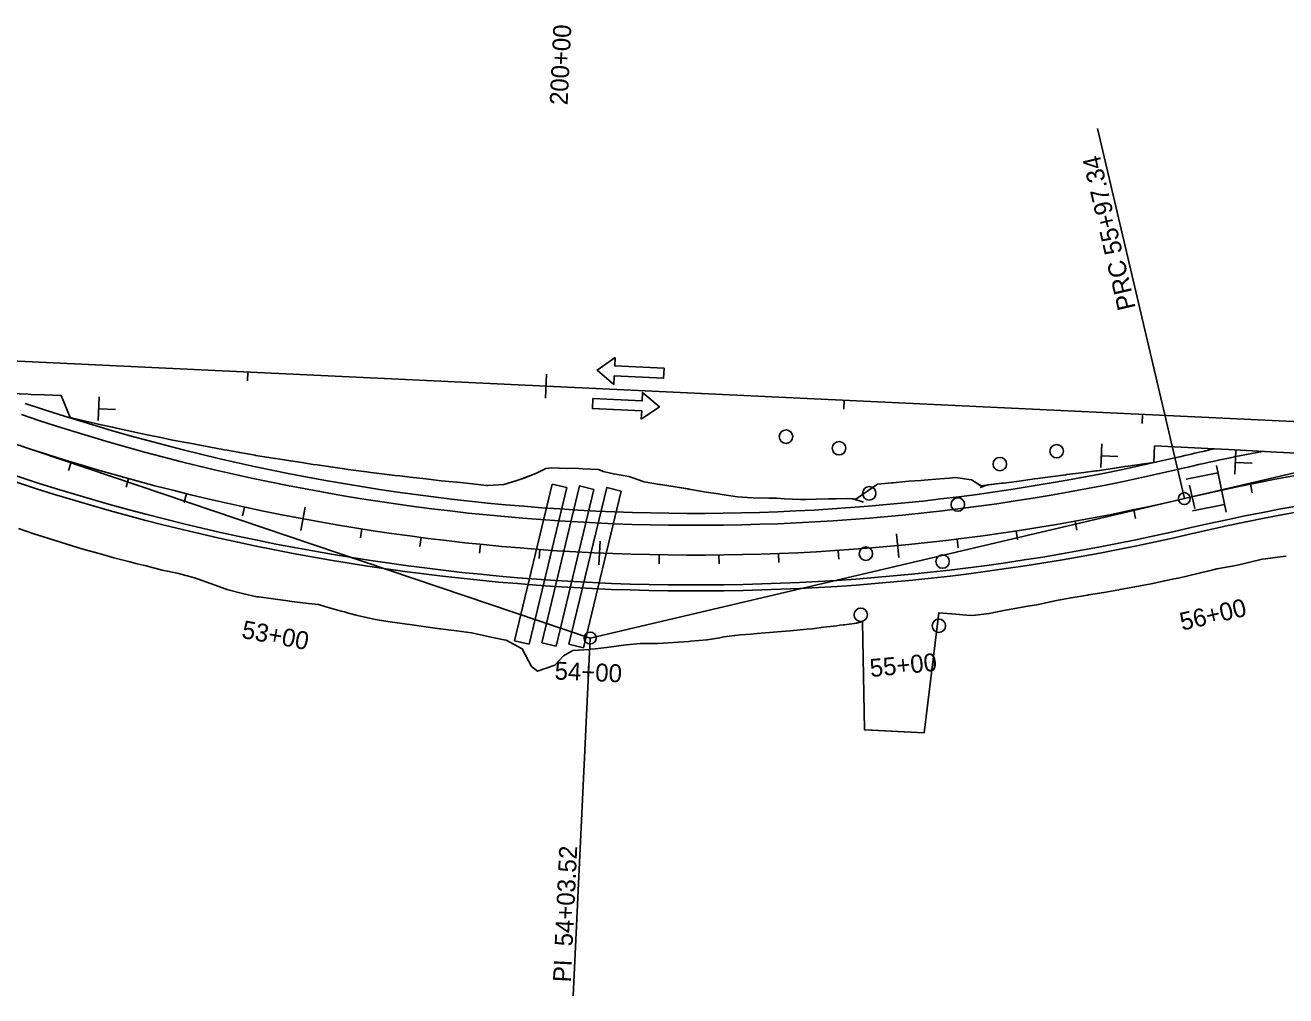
# Model space of a CAD drawing. Extents: x 1140339 to 1165793, y 1646213 to 1669071.
# Drawn here: x 1149058.7 to 1149480.8, y 1657272.9 to 1657598 of the extents above; entities that cross this region are included whole.
import ezdxf

# ---------------------------------------------------------------- set-up
doc = ezdxf.new("R2010")
doc.units = 0
for name, color, linetype in [('Level 47', 7, 'Continuous'), ('R_Horz Alg', 7, 'Continuous'), ('R_Horz Alg Annot', 7, 'Continuous'), ('R_MOT', 7, 'Continuous'), ('R_No Plot', 7, 'Continuous'), ('R_Proposed Const Limits_Cut', 7, 'Continuous'), ('R_Proposed Const Limits_Fill', 7, 'Continuous'), ('R_Proposed Road_Lane', 7, 'Continuous'), ('R_Proposed Road_Shoulder', 7, 'Continuous'), ('R_Water', 7, 'Continuous')]:
    doc.layers.add(name, color=color, linetype=linetype)

msp = doc.modelspace()

# ---------------------------------------------------------------- linework, layer by layer
at = {"layer": 'Level 47'}
for centre in [(1149313.45, 1657460.19), (1149331.21, 1657456.3), (1149404.1, 1657455.3), (1149385.06, 1657451), (1149341.33, 1657441.19), (1149371, 1657437.46), (1149340.2, 1657420.98), (1149365.89, 1657418.35), (1149338.48, 1657400.51), (1149364.64, 1657396.82)]:
    msp.add_circle(centre, 2.25, dxfattribs=at)
at = {"layer": 'R_Horz Alg'}
msp.add_line((1148434, 1657515.04), (1150132.09, 1657434.46), dxfattribs=at)
for centre, start, end in [((1149283.16, 1658136.69), 251.35438, 283.21228), ((1149610.54, 1656742.21), 87.28333, 103.21228)]:
    msp.add_arc(centre, 716.2, start, end, dxfattribs=at)
at = {"layer": 'R_Horz Alg Annot'}
for p, q in [((1149446.85, 1657439.45), (1149417.75, 1657563.41)), ((1149446.85, 1657439.45), (1149544.4, 1657462.35)), ((1149054.18, 1657458.08), (1149247.86, 1657392.73)), ((1149247.86, 1657392.73), (1149446.85, 1657439.45))]:
    msp.add_line(p, q, dxfattribs=at)
for points in [[(1149133.07, 1657478.87), (1149133.21, 1657481.86)], [(1149233.29, 1657481.12), (1149232.91, 1657473.13)], [(1149332.84, 1657469.39), (1149332.98, 1657472.38)], [(1149432.73, 1657464.65), (1149432.87, 1657467.64)], [(1149073.19, 1657448.82), (1149074.06, 1657451.69)], [(1149092.48, 1657443.23), (1149093.27, 1657446.12)], [(1149448.55, 1657443.95), (1149450.34, 1657436.16)], [(1149469.59, 1657441.34), (1149468.99, 1657444.28)], [(1149111.91, 1657438.17), (1149112.63, 1657441.09)], [(1149131.48, 1657433.67), (1149132.12, 1657436.6)], [(1149152.46, 1657436.59), (1149150.99, 1657428.72)], [(1149430.54, 1657432.75), (1149429.93, 1657435.69)], [(1149410.83, 1657428.91), (1149410.3, 1657431.87)], [(1149170.96, 1657426.3), (1149171.43, 1657429.26)], [(1149190.84, 1657423.44), (1149191.23, 1657426.42)], [(1149350.49, 1657427.68), (1149351.25, 1657419.72)], [(1149371.12, 1657422.89), (1149370.75, 1657425.87)], [(1149391.02, 1657425.63), (1149390.57, 1657428.59)], [(1149210.79, 1657421.14), (1149211.1, 1657424.13)], [(1149230.8, 1657419.4), (1149231.02, 1657422.39)], [(1149251.16, 1657425.21), (1149250.81, 1657417.22)], [(1149331.14, 1657419.09), (1149330.94, 1657422.09)], [(1149270.92, 1657417.59), (1149270.97, 1657420.59)], [(1149291.01, 1657417.53), (1149290.97, 1657420.53)], [(1149311.08, 1657418.03), (1149310.97, 1657421.03)], [(1149247.86, 1657392.73), (1149242.17, 1657272.86)]]:
    msp.add_lwpolyline(points, dxfattribs=at)
for centre in [(1149446.85, 1657439.45), (1149247.86, 1657392.73)]:
    msp.add_circle(centre, 2, dxfattribs=at)
at = {"layer": 'R_MOT'}
for p, q in [((1149083.13, 1657465.57), (1149083.46, 1657473.56)), ((1149083.41, 1657469.54), (1149088.86, 1657469.31)), ((1149418.89, 1657449.84), (1149419.22, 1657457.83)), ((1149463.81, 1657447.6), (1149464.14, 1657455.59)), ((1149419.17, 1657453.81), (1149424.63, 1657453.58)), ((1149464.09, 1657451.57), (1149469.55, 1657451.35)), ((1149447.41, 1657445.93), (1149458.11, 1657448.12)), ((1149460.82, 1657434.9), (1149457.61, 1657450.58)), ((1149449.59, 1657435.3), (1149460.29, 1657437.49))]:
    msp.add_line(p, q, dxfattribs=at)
for points in [[(1149256.22, 1657486.69), (1149250.18, 1657482.48), (1149255.8, 1657477.7), (1149255.93, 1657480.51), (1149272.46, 1657479.73), (1149272.62, 1657483.1), (1149256.09, 1657483.88)], [(1149264.99, 1657466), (1149271.04, 1657470.22), (1149265.42, 1657474.99), (1149265.28, 1657472.18), (1149248.75, 1657472.96), (1149248.59, 1657469.59), (1149265.12, 1657468.81)]]:
    msp.add_lwpolyline(points, close=True, dxfattribs=at)
at = {"layer": 'R_No Plot'}
for points in [[(1149048.03, 1657474.84), (1149059.68, 1657474.39), (1149059.68, 1657474.39), (1149060.59, 1657474.36), (1149065.14, 1657474.19), (1149070.58, 1657473.98), (1149070.71, 1657473.97), (1149073.75, 1657466.59), (1149078.29, 1657465.53), (1149078.9, 1657465.38), (1149084.04, 1657464.19), (1149087.85, 1657463.32), (1149089.19, 1657463.02), (1149094.34, 1657461.87), (1149097.43, 1657461.23), (1149099.5, 1657460.8), (1149104.67, 1657459.74), (1149107.02, 1657459.27), (1149109.83, 1657458.71), (1149115.01, 1657457.73), (1149115.52, 1657457.63), (1149116.63, 1657457.43), (1149120.18, 1657456.78), (1149125.35, 1657455.82), (1149126.24, 1657455.65), (1149130.51, 1657454.83), (1149135.69, 1657453.94), (1149135.85, 1657453.92), (1149140.88, 1657453.09), (1149145.49, 1657452.37), (1149146.06, 1657452.28), (1149151.25, 1657451.49), (1149155.13, 1657450.9), (1149156.44, 1657450.7), (1149161.63, 1657449.94), (1149164.77, 1657449.5), (1149166.82, 1657449.22), (1149172.01, 1657448.53), (1149173.06, 1657448.39), (1149174.43, 1657448.21), (1149177.21, 1657447.85), (1149182.41, 1657447.21), (1149184.08, 1657447.01), (1149187.61, 1657446.6), (1149192.81, 1657446.02), (1149193.75, 1657445.9), (1149198.01, 1657445.4), (1149203.23, 1657444.94), (1149203.43, 1657444.93), (1149208.43, 1657444.38), (1149213.09, 1657443.83), (1149213.62, 1657443.77), (1149218.92, 1657444.16), (1149222.98, 1657445.38), (1149224.3, 1657445.78), (1149225.43, 1657446.22)], [(1149436.62, 1657451.54), (1149436.91, 1657457.1), (1149456.99, 1657456.08)], [(1149456.99, 1657456.08), (1149461.68, 1657455.84), (1149477.76, 1657455.02), (1149493.85, 1657454.2), (1149514.25, 1657453.18), (1149534.65, 1657452.17), (1149548.5, 1657451.54), (1149562.35, 1657450.92), (1149576.21, 1657450.3), (1149590.06, 1657449.68), (1149605.38, 1657448.9), (1149620.71, 1657448.13), (1149636.03, 1657447.36), (1149643.98, 1657446.96)], [(1149378.8, 1657443.73), (1149385.78, 1657444.58), (1149386.3, 1657444.64), (1149388.1, 1657444.86), (1149391.51, 1657445.3), (1149396.72, 1657446.02), (1149397.79, 1657446.17), (1149401.94, 1657446.73), (1149407.15, 1657447.45), (1149407.48, 1657447.49), (1149412.39, 1657448.09), (1149417.2, 1657448.71), (1149417.62, 1657448.76), (1149422.84, 1657449.51), (1149426.9, 1657450.14), (1149428.06, 1657450.32), (1149433.29, 1657451.06), (1149436.62, 1657451.54)], [(1149225.43, 1657446.22), (1149229.69, 1657447.87), (1149233, 1657449.55), (1149235.02, 1657449.78), (1149240.19, 1657449.53), (1149242.64, 1657449.59), (1149245.37, 1657449.46), (1149250.54, 1657449.24), (1149250.54, 1657449.24), (1149250.95, 1657449.07), (1149252.21, 1657448.56), (1149255.65, 1657447.69), (1149260.81, 1657446.85), (1149261.77, 1657446.49), (1149265.95, 1657445.03), (1149271.13, 1657444.18), (1149271.38, 1657444.15), (1149276.33, 1657443.38), (1149280.73, 1657442.68)], [(1149336.8, 1657439.25), (1149344.13, 1657444.31), (1149348.88, 1657444.71), (1149349.33, 1657444.75), (1149350.3, 1657444.84), (1149354.53, 1657445.24), (1149358.55, 1657445.55), (1149359.74, 1657445.64), (1149364.96, 1657446.03), (1149368.24, 1657446.29), (1149370.17, 1657446.45), (1149375.55, 1657445.68), (1149378.8, 1657443.73)], [(1149280.73, 1657442.68), (1149281.04, 1657442.63), (1149281.54, 1657442.53), (1149286.76, 1657441.55), (1149290.75, 1657441.01), (1149291.99, 1657440.85), (1149297.24, 1657440.04), (1149300.5, 1657439.76), (1149302.48, 1657439.71), (1149307.73, 1657439.61), (1149310.25, 1657439.57), (1149312.99, 1657439.37), (1149318.25, 1657439.11), (1149320.02, 1657439.14), (1149323.5, 1657439.21), (1149327.71, 1657439.31), (1149328.75, 1657439.34), (1149329.78, 1657439.37), (1149330.2, 1657439.38), (1149334.01, 1657439.49), (1149336.8, 1657439.25)], [(1149480.94, 1657420.17), (1149478.09, 1657419.83), (1149474.03, 1657419.3), (1149472.95, 1657419.09), (1149467.89, 1657417.92), (1149464.63, 1657417.16), (1149462.84, 1657416.75), (1149457.72, 1657415.85), (1149455.17, 1657415.27), (1149452.67, 1657414.67), (1149452.67, 1657414.67), (1149447.26, 1657413.33), (1149445.27, 1657412.94), (1149441.78, 1657412.27), (1149436.35, 1657411.02), (1149435.15, 1657410.75), (1149430.88, 1657409.95), (1149425.39, 1657409), (1149424.96, 1657408.92), (1149419.92, 1657407.93), (1149414.76, 1657407.15), (1149414.41, 1657407.1), (1149408.91, 1657406.22), (1149404.56, 1657405.39), (1149403.45, 1657405.14), (1149397.99, 1657403.97), (1149394.4, 1657403.35), (1149392.49, 1657403.05), (1149391.95, 1657402.96), (1149387.01, 1657402.02), (1149384.2, 1657401.48), (1149381.52, 1657400.98), (1149376, 1657400.25), (1149373.89, 1657400.42), (1149370.33, 1657400.71), (1149364.67, 1657401.2), (1149359.74, 1657360.99), (1149340.06, 1657361.98), (1149339.76, 1657361.94), (1149339.1, 1657398.26), (1149337.05, 1657397.75), (1149333.05, 1657397.17), (1149332.61, 1657397.11), (1149331.52, 1657396.98), (1149330.42, 1657396.84), (1149325.98, 1657396.31), (1149322.31, 1657395.86), (1149320.44, 1657395.66), (1149314.88, 1657395.17), (1149311.98, 1657394.94), (1149309.31, 1657394.73), (1149303.75, 1657394.23), (1149301.64, 1657394.05), (1149298.17, 1657393.77), (1149292.6, 1657393.12), (1149291.28, 1657392.83), (1149287.01, 1657392.17), (1149281.42, 1657391.66), (1149280.89, 1657391.61), (1149275.82, 1657391.24), (1149270.47, 1657390.93), (1149270.21, 1657390.92), (1149264.6, 1657390.84), (1149260.04, 1657390.42), (1149258.97, 1657390.28), (1149253.33, 1657389.58), (1149249.54, 1657389.13), (1149248.13, 1657388.97), (1149247.68, 1657388.91), (1149247.67, 1657388.91), (1149242.02, 1657388.54), (1149238.94, 1657386.77), (1149236.07, 1657383.65), (1149230.25, 1657381.61), (1149228.16, 1657383.16), (1149225.13, 1657389.16), (1149219.72, 1657392), (1149218.36, 1657392.28), (1149214.18, 1657393.15), (1149208.66, 1657394.33), (1149208.1, 1657394.46), (1149203.11, 1657395.1), (1149197.77, 1657395.8), (1149197.55, 1657395.83), (1149192, 1657396.59), (1149187.45, 1657397.22), (1149186.45, 1657397.36), (1149180.9, 1657398.13), (1149177.15, 1657398.72), (1149175.37, 1657399.07), (1149169.89, 1657400.26), (1149166.98, 1657401.06), (1149165.55, 1657401.46), (1149164.46, 1657401.76), (1149159.05, 1657403.29), (1149156.92, 1657403.91), (1149153.55, 1657404.31), (1149148, 1657405), (1149146.6, 1657405.18), (1149142.44, 1657405.73), (1149136.89, 1657406.49), (1149136.28, 1657406.57), (1149131.41, 1657407.63), (1149126.17, 1657409.03), (1149126, 1657409.09), (1149120.69, 1657410.96), (1149116.31, 1657412.54), (1149115.4, 1657412.87), (1149110, 1657414.31), (1149106.26, 1657415.12), (1149105.09, 1657415.38), (1149104.55, 1657415.51), (1149099.13, 1657416.86), (1149096.19, 1657417.62), (1149093.72, 1657418.24), (1149088.32, 1657419.63), (1149086.15, 1657420.23), (1149082.94, 1657421.14), (1149077.57, 1657422.65), (1149076.17, 1657423.06), (1149072.22, 1657424.26), (1149066.89, 1657425.94), (1149066.26, 1657426.14), (1149061.58, 1657427.64), (1149056.41, 1657429.39)]]:
    msp.add_lwpolyline(points, dxfattribs=at)
at = {"layer": 'R_Proposed Const Limits_Cut'}
msp.add_lwpolyline([(1149339.17, 1657440.84), (1149339.44, 1657441.07), (1149344.13, 1657444.31), (1149348.88, 1657444.71), (1149349.33, 1657444.75), (1149350.3, 1657444.84), (1149354.53, 1657445.24), (1149358.55, 1657445.55), (1149359.74, 1657445.64), (1149364.96, 1657446.03), (1149368.24, 1657446.29), (1149370.17, 1657446.45), (1149375.55, 1657445.68), (1149378.36, 1657443.99)], dxfattribs=at)
at = {"layer": 'R_Proposed Const Limits_Fill'}
for points in [[(1149048.03, 1657474.84), (1149059.68, 1657474.39), (1149059.68, 1657474.39), (1149060.59, 1657474.36), (1149065.14, 1657474.19), (1149070.58, 1657473.98), (1149070.71, 1657473.97), (1149073.75, 1657466.59), (1149078.29, 1657465.53), (1149078.9, 1657465.38), (1149084.04, 1657464.19), (1149087.85, 1657463.32), (1149089.19, 1657463.02), (1149094.34, 1657461.87), (1149097.43, 1657461.23), (1149099.5, 1657460.8), (1149104.67, 1657459.74), (1149107.02, 1657459.27), (1149109.83, 1657458.71), (1149115.01, 1657457.73), (1149115.52, 1657457.63), (1149116.63, 1657457.43), (1149120.18, 1657456.78), (1149125.35, 1657455.82), (1149126.24, 1657455.65), (1149130.51, 1657454.83), (1149135.69, 1657453.94), (1149135.85, 1657453.92), (1149140.88, 1657453.09), (1149145.49, 1657452.37), (1149146.06, 1657452.28), (1149151.25, 1657451.49), (1149155.13, 1657450.9), (1149156.44, 1657450.7), (1149161.63, 1657449.94), (1149164.77, 1657449.5), (1149166.82, 1657449.22), (1149172.01, 1657448.53), (1149173.06, 1657448.39), (1149174.43, 1657448.21), (1149177.21, 1657447.85), (1149182.41, 1657447.21), (1149184.08, 1657447.01), (1149187.61, 1657446.6), (1149192.81, 1657446.02), (1149193.75, 1657445.9), (1149198.01, 1657445.4), (1149203.23, 1657444.94), (1149203.43, 1657444.93), (1149208.43, 1657444.38), (1149213.09, 1657443.83), (1149213.62, 1657443.77), (1149218.92, 1657444.16), (1149222.98, 1657445.38), (1149224.3, 1657445.78), (1149229.69, 1657447.87), (1149233, 1657449.55), (1149235.02, 1657449.78), (1149240.19, 1657449.53), (1149242.64, 1657449.59), (1149245.37, 1657449.46), (1149250.54, 1657449.24), (1149250.54, 1657449.24), (1149250.95, 1657449.07), (1149252.21, 1657448.56), (1149255.65, 1657447.69), (1149260.81, 1657446.85), (1149261.77, 1657446.49), (1149265.95, 1657445.03), (1149271.13, 1657444.18), (1149271.38, 1657444.15), (1149276.33, 1657443.38), (1149281.04, 1657442.63), (1149281.54, 1657442.53), (1149286.76, 1657441.55), (1149290.75, 1657441.01), (1149291.99, 1657440.85), (1149297.24, 1657440.04), (1149300.5, 1657439.76), (1149302.48, 1657439.71), (1149307.73, 1657439.61), (1149310.25, 1657439.57), (1149312.99, 1657439.37), (1149318.25, 1657439.11), (1149320.02, 1657439.14), (1149323.5, 1657439.21), (1149327.71, 1657439.31), (1149328.75, 1657439.34), (1149329.78, 1657439.37), (1149330.2, 1657439.38), (1149334.01, 1657439.49), (1149335.99, 1657439.32), (1149339.38, 1657438.19)], [(1149436.62, 1657451.54), (1149436.91, 1657457.1), (1149456.99, 1657456.08)], [(1149378.48, 1657443.13), (1149381.08, 1657444), (1149385.78, 1657444.58), (1149386.3, 1657444.64), (1149388.1, 1657444.86), (1149391.51, 1657445.3), (1149396.72, 1657446.02), (1149397.79, 1657446.17), (1149401.94, 1657446.73), (1149407.15, 1657447.45), (1149407.48, 1657447.49), (1149412.39, 1657448.09), (1149417.2, 1657448.71), (1149417.62, 1657448.76), (1149422.84, 1657449.51), (1149426.9, 1657450.14), (1149428.06, 1657450.32), (1149433.29, 1657451.06), (1149436.62, 1657451.54)], [(1149056.41, 1657429.39), (1149061.58, 1657427.64), (1149066.26, 1657426.14), (1149066.89, 1657425.94), (1149072.22, 1657424.26), (1149076.17, 1657423.06), (1149077.57, 1657422.65), (1149082.94, 1657421.14), (1149086.15, 1657420.23), (1149088.32, 1657419.63), (1149093.72, 1657418.24), (1149096.19, 1657417.62), (1149099.13, 1657416.86), (1149104.55, 1657415.51), (1149105.09, 1657415.38), (1149106.26, 1657415.12), (1149110, 1657414.31), (1149115.4, 1657412.87), (1149116.31, 1657412.54), (1149120.69, 1657410.96), (1149126, 1657409.09), (1149126.17, 1657409.03), (1149131.41, 1657407.63), (1149136.28, 1657406.57), (1149136.89, 1657406.49), (1149142.44, 1657405.73), (1149146.6, 1657405.18), (1149148, 1657405), (1149153.55, 1657404.31), (1149156.92, 1657403.91), (1149159.05, 1657403.29), (1149164.46, 1657401.76), (1149165.55, 1657401.46), (1149166.98, 1657401.06), (1149169.89, 1657400.26), (1149175.37, 1657399.07), (1149177.15, 1657398.72), (1149180.9, 1657398.13), (1149186.45, 1657397.36), (1149187.45, 1657397.22), (1149192, 1657396.59), (1149197.55, 1657395.83), (1149197.77, 1657395.8), (1149203.11, 1657395.1), (1149208.1, 1657394.46), (1149208.66, 1657394.33), (1149214.18, 1657393.15), (1149218.36, 1657392.28), (1149219.72, 1657392), (1149225.13, 1657389.16), (1149228.16, 1657383.16), (1149230.25, 1657381.61), (1149236.07, 1657383.65), (1149238.94, 1657386.77), (1149242.02, 1657388.54), (1149247.67, 1657388.91), (1149247.68, 1657388.91), (1149248.13, 1657388.97), (1149249.54, 1657389.13), (1149253.33, 1657389.58), (1149258.97, 1657390.28), (1149260.04, 1657390.42), (1149264.6, 1657390.84), (1149270.21, 1657390.92), (1149270.47, 1657390.93), (1149275.82, 1657391.24), (1149280.89, 1657391.61), (1149281.42, 1657391.66), (1149287.01, 1657392.17), (1149291.28, 1657392.83), (1149292.6, 1657393.12), (1149298.17, 1657393.77), (1149301.64, 1657394.05), (1149303.75, 1657394.23), (1149309.31, 1657394.73), (1149311.98, 1657394.94), (1149314.88, 1657395.17), (1149320.44, 1657395.66), (1149322.31, 1657395.86), (1149325.98, 1657396.31), (1149330.42, 1657396.84), (1149331.52, 1657396.98), (1149332.61, 1657397.11), (1149333.05, 1657397.17), (1149337.05, 1657397.75), (1149339.1, 1657398.26), (1149339.76, 1657361.94), (1149359.74, 1657360.99), (1149364.67, 1657401.2), (1149370.33, 1657400.71), (1149373.89, 1657400.42), (1149376, 1657400.25), (1149381.52, 1657400.98), (1149384.2, 1657401.48), (1149387.01, 1657402.02), (1149391.95, 1657402.96), (1149392.49, 1657403.05), (1149394.4, 1657403.35), (1149397.99, 1657403.97), (1149403.45, 1657405.14), (1149404.56, 1657405.39), (1149408.91, 1657406.22), (1149414.41, 1657407.1), (1149414.76, 1657407.15), (1149419.92, 1657407.93), (1149424.96, 1657408.92), (1149425.39, 1657409), (1149430.88, 1657409.95), (1149435.15, 1657410.75), (1149436.35, 1657411.02), (1149441.78, 1657412.27), (1149445.27, 1657412.94), (1149447.26, 1657413.33), (1149452.67, 1657414.67), (1149452.67, 1657414.67), (1149455.17, 1657415.27), (1149457.72, 1657415.85), (1149462.84, 1657416.75), (1149464.63, 1657417.16), (1149467.89, 1657417.92), (1149472.95, 1657419.09), (1149474.03, 1657419.3), (1149478.09, 1657419.83), (1149480.94, 1657420.17)]]:
    msp.add_lwpolyline(points, dxfattribs=at)
at = {"layer": 'R_Proposed Road_Lane'}
msp.add_lwpolyline([(1149643.98, 1657446.96), (1149636.03, 1657447.36), (1149620.71, 1657448.13), (1149605.38, 1657448.9), (1149590.06, 1657449.68), (1149576.21, 1657450.3), (1149562.35, 1657450.92), (1149548.5, 1657451.54), (1149534.65, 1657452.17), (1149514.25, 1657453.18), (1149493.85, 1657454.2), (1149477.76, 1657455.02), (1149461.68, 1657455.84), (1149456.99, 1657456.08)], dxfattribs=at)
for centre, radius, start, end in [((1149283.16, 1658136.69), 706.2, 251.35438, 283.21228), ((1149610.54, 1656742.21), 726.2, 100.91784, 103.21228), ((1149283.16, 1658136.69), 726.2, 251.35438, 283.21228), ((1149608.18, 1656741.99), 705.87, 87.09231, 103.02126)]:
    msp.add_arc(centre, radius, start, end, dxfattribs=at)
at = {"layer": 'R_Proposed Road_Shoulder'}
for centre, radius, start, end in [((1149283.16, 1658136.69), 702.2, 251.35438, 283.21228), ((1149610.54, 1656742.21), 730.2, 102.13931, 103.21228), ((1149283.16, 1658136.69), 728.2, 251.35438, 283.21228), ((1149608.18, 1656741.99), 703.87, 87.09231, 103.02126)]:
    msp.add_arc(centre, radius, start, end, dxfattribs=at)
at = {"layer": 'R_Water'}
for p, q in [((1149235.15, 1657444.32), (1149222.52, 1657391.82)), ((1149240.01, 1657443.15), (1149227.38, 1657390.65)), ((1149244.26, 1657443.68), (1149231.62, 1657391.17)), ((1149240.01, 1657443.15), (1149235.15, 1657444.32)), ((1149253.39, 1657443.15), (1149240.75, 1657390.65)), ((1149244.26, 1657443.68), (1149249.12, 1657442.51)), ((1149258.25, 1657441.98), (1149253.39, 1657443.15)), ((1149249.12, 1657442.51), (1149236.48, 1657390)), ((1149258.25, 1657441.98), (1149245.61, 1657389.48)), ((1149227.38, 1657390.65), (1149222.52, 1657391.82)), ((1149236.48, 1657390), (1149231.62, 1657391.17)), ((1149245.61, 1657389.48), (1149240.75, 1657390.65))]:
    msp.add_line(p, q, dxfattribs=at)

# ---------------------------------------------------------------- texts
at = {"layer": 'R_Horz Alg Annot'}
for s, rotation, p in [('200+00', 87.2833, (1149240.29, 1657571.16)), ('PRC 55+97.34', 103.2123, (1149430.58, 1657503.32)), ('56+00', 12.9991, (1149446.11, 1657395.15)), ('53+00', 349.4254, (1149130.85, 1657392.81)), ('54+00', 357.4254, (1149235.86, 1657378.85)), ('55+00', 5.4254, (1149341.79, 1657379.64)), ('PI  54+03.52', 87.2833, (1149241.38, 1657277.3))]:
    msp.add_text(s, height=6, rotation=rotation, dxfattribs=at).set_placement(p)

doc.saveas('drawing.dxf')
